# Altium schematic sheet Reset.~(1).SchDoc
size A4
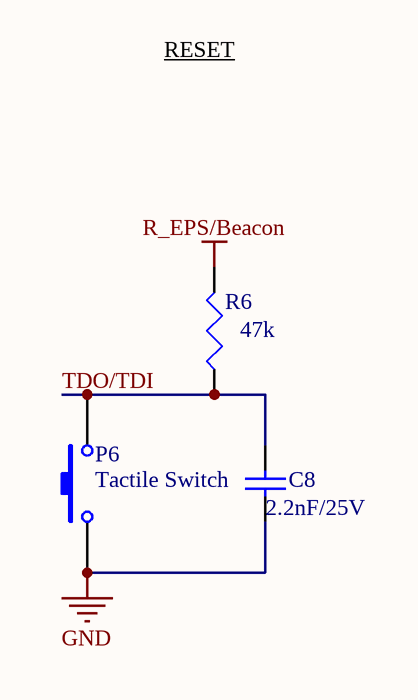
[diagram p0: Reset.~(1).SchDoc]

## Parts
C8  value 2.2nF/25V  [C1206]
P6  Tactile Switch  [SPST-2]
R6  value 47k  [J1-0603]  (hidden comment: Res3)

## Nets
GND: C8.2 P6.1
R_EPS/Beacon: R6.2
TDO/TDI: C8.1 P6.2 R6.1

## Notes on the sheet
- RESET

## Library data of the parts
C8 = Cap Semi: Capacitor (Semiconductor SIM Model)
P6 = SW-PB: Switch
R6 = Res3: Resistor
